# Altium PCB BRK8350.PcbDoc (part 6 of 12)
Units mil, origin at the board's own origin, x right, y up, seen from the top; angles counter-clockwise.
Board outline 9448.82 x 5905.51 mil, 8 copper layers (L1-TOP, L2-GND, L3-SIG, L4-GND, L5-PWR, L6-PWR, L7-GND, L8-BOT), stack 57.69 mil thick; 288 components, 543 nets, 1891 pads, 2032 vias.
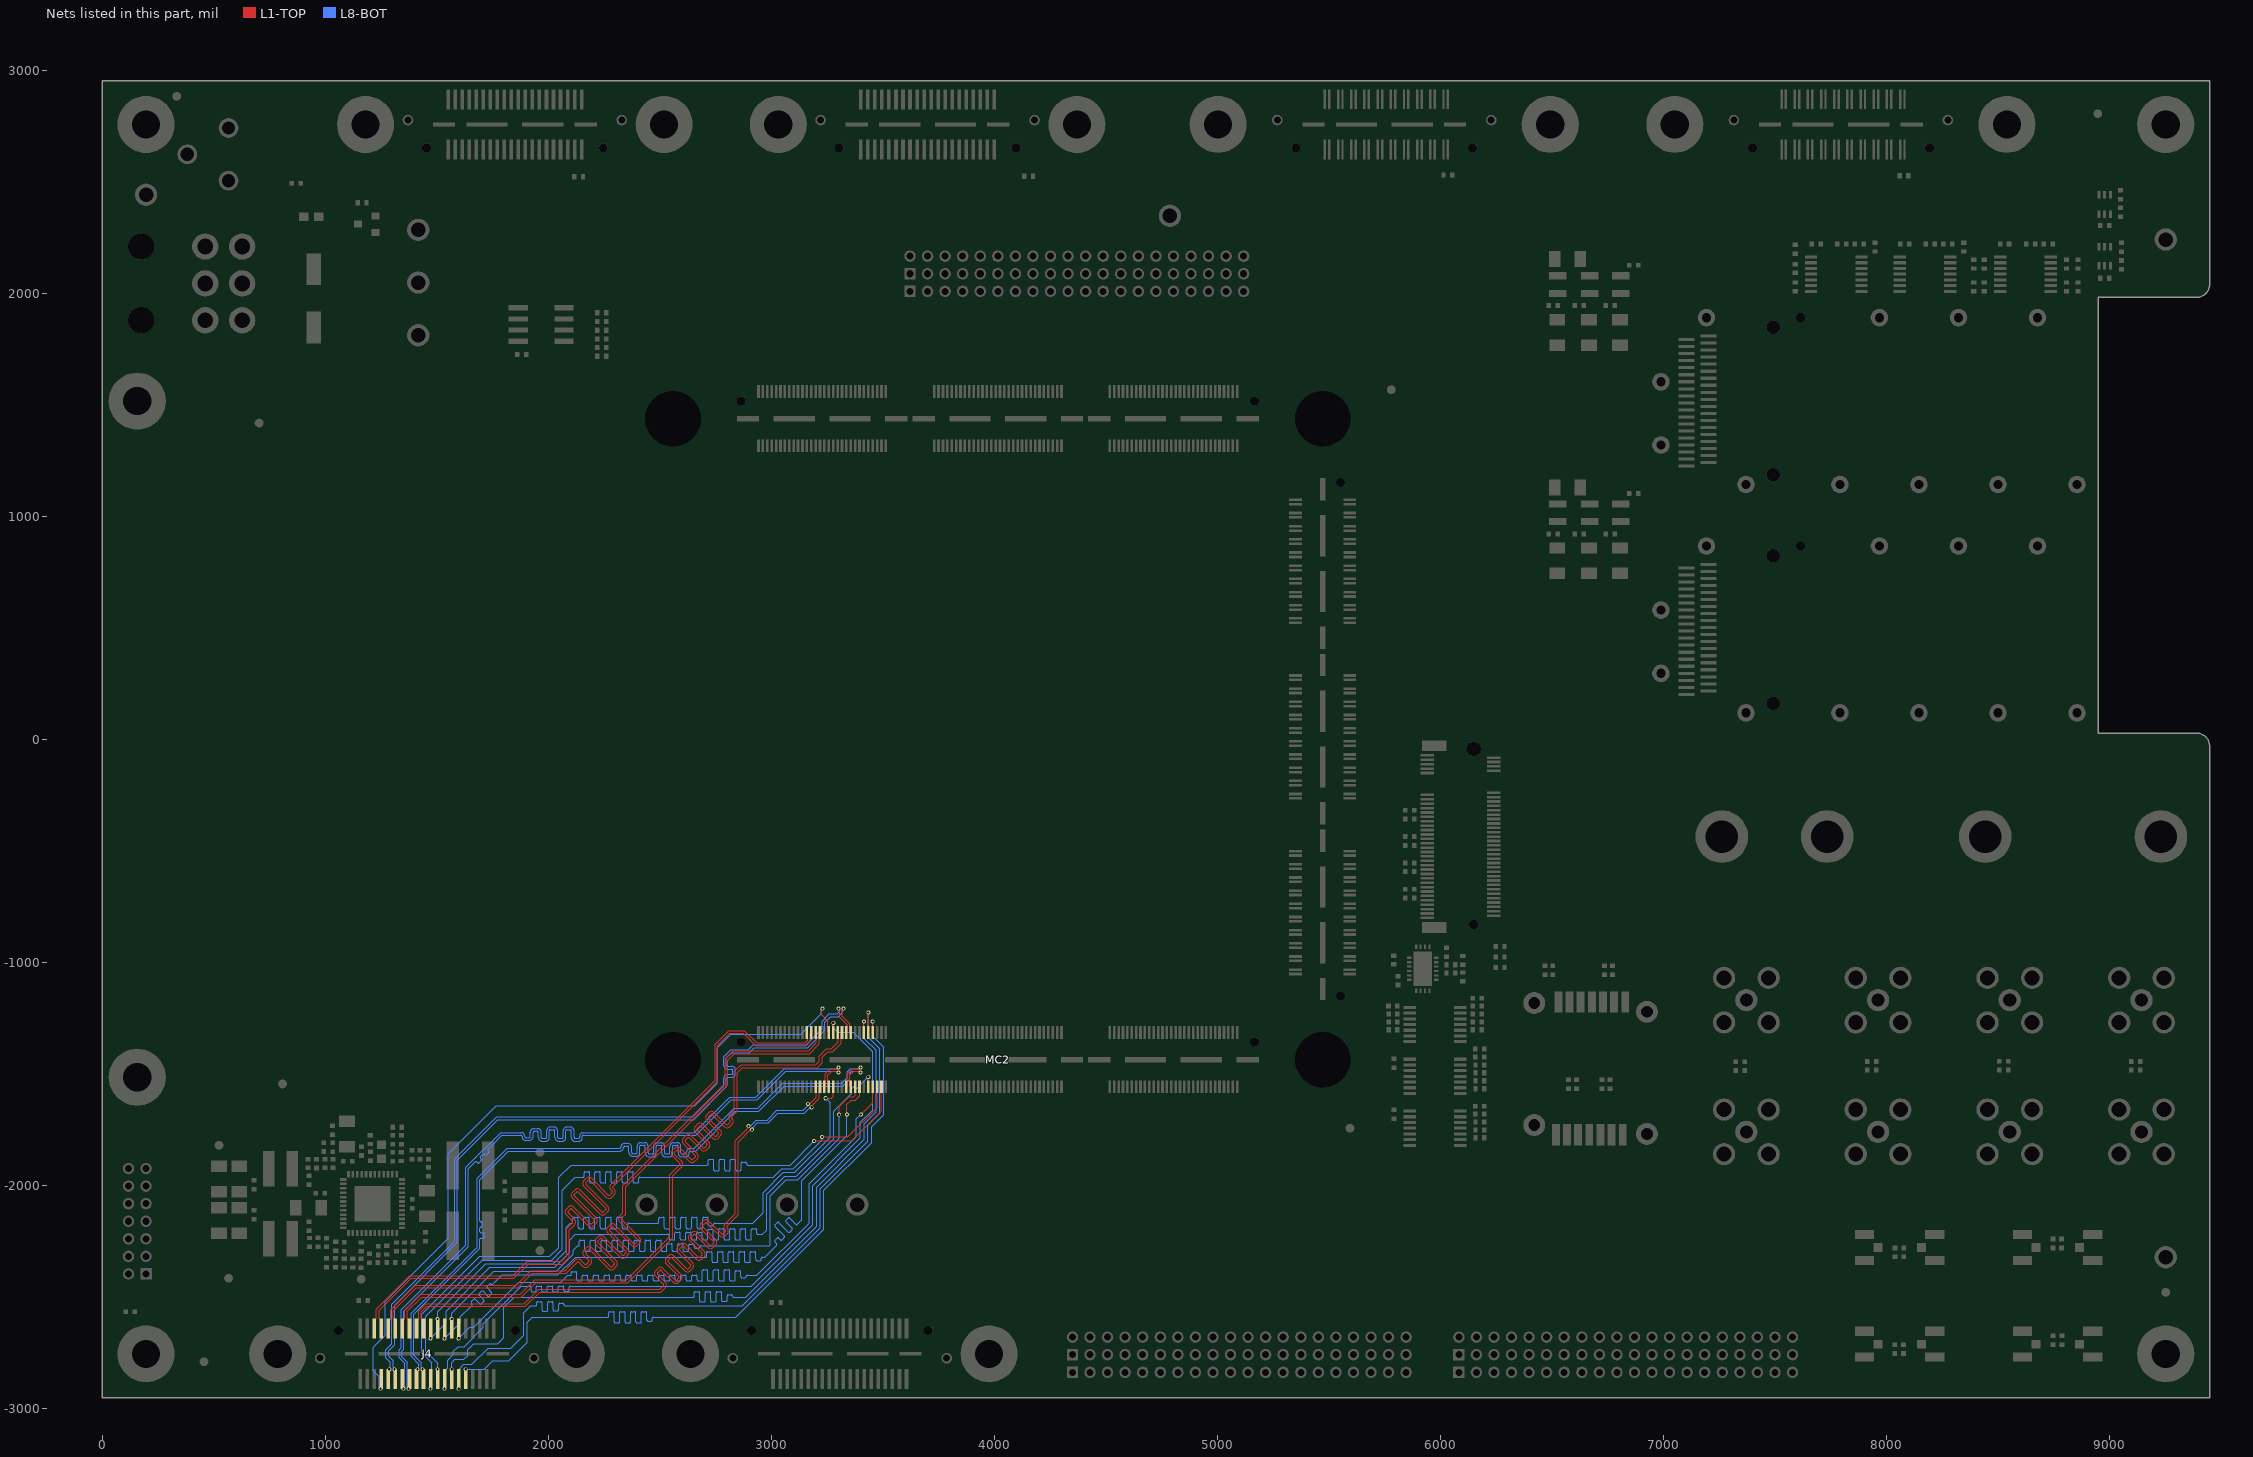
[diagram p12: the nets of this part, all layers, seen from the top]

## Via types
v1: diameter 18, hole 10, L1-TOP to L8-BOT, tented both sides, 2032 vias

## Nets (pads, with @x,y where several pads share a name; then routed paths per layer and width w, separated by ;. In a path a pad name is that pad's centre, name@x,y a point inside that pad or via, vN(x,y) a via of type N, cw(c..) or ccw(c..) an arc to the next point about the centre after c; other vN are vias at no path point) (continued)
PORTB_S1_D1P: J4.6 MC2.23 | length 3537.4
  L1-TOP w4.2: J4.6@1220.44,-2643.11 1220.44,-2606.36 1226.34,-2600.46 1227.43,-2600.46 1229.89,-2598 1229.89,-2555.26 1379.67,-2405.48 1840.24,-2405.48 1904.92,-2340.81 2058.46,-2340.81 2082.68,-2316.59 2082.68,-2207.32 2082.68,-2194.72 2091.59,-2185.81 2108.91,-2168.49 ccw(c2105.49,-2165.07) 2108.89,-2161.63 2079.99,-2132.72 cw(c2092.32,-2120.39) 2079.99,-2108.06 2090.25,-2097.79 cw(c2102.59,-2110.12) 2114.92,-2097.79 2188.76,-2171.64 ccw(c2192.19,-2168.22) 2195.61,-2171.64 2205.88,-2161.37 ccw(c2202.45,-2157.95) 2205.88,-2154.53 2107.93,-2056.58 cw(c2120.26,-2044.25) 2107.93,-2031.92 2118.2,-2021.65 cw(c2130.53,-2033.98) 2142.86,-2021.65 2240.81,-2119.59 ccw(c2244.23,-2116.17) 2247.65,-2119.59 2257.92,-2109.33 ccw(c2254.5,-2105.91) 2257.92,-2102.48 2159.98,-2004.54 cw(c2172.31,-1992.21) 2159.98,-1979.88 2170.24,-1969.61 cw(c2182.57,-1981.94) 2194.91,-1969.61 2269.7,-2044.4 ; 2269.7,-2044.4 ccw(c2273.12,-2040.98) 2276.55,-2044.4 ; 2276.55,-2044.4 2286.81,-2034.14 ccw(c2283.39,-2030.72) 2286.81,-2027.29 2280.79,-2021.27 cw(c2293.12,-2008.94) 2280.79,-1996.61 2286.73,-1990.67 2748.03,-1529.37 2748.03,-1368.01 2809.74,-1306.3 2879.23,-1306.3 2935.14,-1362.2 3150.98,-1362.2 3163.01,-1350.18 3163.01,-1318.88 MC2.23@3159.46,-1315.34
PORTB_S2_D0N: J4.7 MC2.33 | length 3378.8
  L1-TOP w4.2: v1(3229.36,-1208.57) 3228.43,-1208.57 3224.41,-1212.6 3224.41,-1234.15 3254.35,-1264.09 3254.35,-1311.8 MC2.33@3257.89,-1315.34
  L8-BOT w4.2: v1(1247.73,-2912.07) 1247.73,-2908.34 1242.49,-2903.1 1242.49,-2859.39 1214.64,-2831.54 1214.64,-2726.3 1269.03,-2671.92 1269.03,-2520.39 1551.18,-2238.23 1551.18,-1859.19 1767.85,-1642.52 2656.63,-1642.52 2757.41,-1541.74 2757.41,-1384.32 2818.9,-1322.83 2905.51,-1322.83 3131.66,-1322.83 3214.34,-1240.16 3224.41,-1230.08 3224.41,-1217.26 3229.36,-1212.31 v1(3229.36,-1208.57)
PORTB_S3_D1N: J4.8 MC2.25 | length 3537.5
  L1-TOP w4.2: J4.8@1251.94,-2643.11 1251.94,-2606.36 1246.04,-2600.46 1244.95,-2600.46 1242.49,-2598 1242.49,-2560.48 1384.89,-2418.08 1845.46,-2418.08 1910.14,-2353.41 2063.68,-2353.41 2095.28,-2321.81 2095.28,-2199.94 2100.5,-2194.72 2117.82,-2177.4 ccw(c2105.49,-2165.07) 2119.66,-2154.91 2119.66,-2154.58 2117.84,-2152.76 ; 2117.82,-2152.74 2088.9,-2123.81 cw(c2092.32,-2120.39) 2088.9,-2116.97 2099.16,-2106.7 cw(c2102.59,-2110.12) 2106.01,-2106.7 2179.85,-2180.55 ccw(c2192.19,-2168.22) 2204.52,-2180.55 2214.78,-2170.28 ccw(c2202.45,-2157.95) 2214.78,-2145.62 2116.84,-2047.67 cw(c2120.26,-2044.25) 2116.84,-2040.83 2127.11,-2030.56 cw(c2130.53,-2033.98) 2133.95,-2030.56 2231.9,-2128.5 ccw(c2244.23,-2116.17) 2256.56,-2128.5 2266.83,-2118.24 ccw(c2254.5,-2105.91) 2266.83,-2093.57 2168.89,-1995.63 cw(c2172.31,-1992.21) 2168.89,-1988.79 2179.15,-1978.52 cw(c2182.57,-1981.94) 2186,-1978.52 2260.79,-2053.31 ccw(c2273.12,-2040.98) 2285.46,-2053.31 2295.72,-2043.05 ccw(c2283.39,-2030.72) 2295.72,-2018.38 2289.7,-2012.36 cw(c2293.12,-2008.94) 2289.7,-2005.52 2295.64,-1999.58 2760.63,-1534.58 2760.63,-1373.23 2814.96,-1318.9 2874.02,-1318.9 2929.92,-1374.8 3156.2,-1374.8 3175.61,-1355.4 3175.61,-1318.88 MC2.25@3179.15,-1315.34
PORTB_S4_D2P: J4.9 MC2.41 | length 3378.6
  L1-TOP w4.2: v1(3301.35,-1208.66) 3303.81,-1211.12 3306.3,-1211.12 3306.3,-1247.23 3340.17,-1281.1 3340.17,-1311.8 MC2.41@3336.63,-1315.34
  L8-BOT w4.2: v1(1287.76,-2825.36) 1287.76,-2821.62 1292.26,-2817.12 1292.26,-2792.82 1272.24,-2772.8 1272.24,-2736.55 1298.23,-2710.56 1298.23,-2532.48 1580.38,-2250.33 1580.38,-1882.11 1769.58,-1692.91 2647.54,-1692.91 2786.61,-1553.84 2786.61,-1546.93 2786.61,-1520.73 cw(c2804.05,-1520.73) 2804.05,-1503.29 2821.89,-1503.29 ccw(c2821.89,-1498.45) 2826.73,-1498.45 2826.73,-1483.93 ccw(c2821.89,-1483.93) 2821.89,-1479.09 2804.05,-1479.09 cw(c2804.05,-1461.65) 2786.61,-1461.65 2786.61,-1453.25 2786.61,-1423.91 2817.62,-1392.91 2896.36,-1392.91 2919.19,-1370.08 3157.48,-1370.08 3228.29,-1299.27 3228.29,-1263.69 3260.48,-1231.49 3295.28,-1231.49 3306.3,-1220.47 3306.3,-1217.35 3301.35,-1212.4 v1(3301.35,-1208.66)
PORTB_S5_D3P: J4.10 MC2.27 | length 3537.5
  L1-TOP w4.2: J4.10@1283.44,-2643.11 1283.44,-2606.36 1289.34,-2600.46 1290.43,-2600.46 1292.89,-2598 1292.89,-2558.14 1403.75,-2447.28 1857.56,-2447.28 1922.23,-2382.61 2075.77,-2382.61 2092.95,-2365.43 2121.89,-2336.49 cw(c2134.22,-2348.82) 2144.38,-2334.65 2144.71,-2334.65 2146.53,-2336.47 ; 2146.56,-2336.49 2164.43,-2354.36 ccw(c2167.85,-2350.94) 2171.27,-2354.36 2181.54,-2344.09 ccw(c2178.12,-2340.67) 2181.54,-2337.25 2159.94,-2315.65 cw(c2172.27,-2303.32) 2159.94,-2290.99 2170.21,-2280.72 cw(c2182.54,-2293.05) 2194.87,-2280.72 2279.48,-2365.33 ccw(c2282.9,-2361.91) 2286.32,-2365.33 2296.59,-2355.06 ; 2296.59,-2355.06 ccw(c2293.17,-2351.64) 2296.59,-2348.22 2213.94,-2265.57 cw(c2226.27,-2253.24) 2213.94,-2240.9 2224.21,-2230.64 cw(c2236.54,-2242.97) 2248.87,-2230.64 2331.52,-2313.29 ccw(c2334.95,-2309.86) 2338.37,-2313.29 2348.64,-2303.02 ccw(c2345.21,-2299.6) 2348.64,-2296.17 2265.99,-2213.52 cw(c2278.32,-2201.19) 2265.98,-2188.86 2276.25,-2178.59 cw(c2288.58,-2190.93) 2300.92,-2178.59 2383.57,-2261.24 ccw(c2386.99,-2257.82) 2390.41,-2261.24 2400.68,-2250.98 ccw(c2397.26,-2247.55) 2400.68,-2244.13 2319.8,-2163.25 cw(c2332.13,-2150.92) 2319.8,-2138.59 2325.74,-2132.65 2334.65,-2123.74 2334.65,-2012.3 2334.65,-2001.87 2792.85,-1543.67 2792.85,-1433.43 2829.43,-1396.85 3167.03,-1396.85 3202.38,-1361.5 3202.38,-1318.88 MC2.27@3198.83,-1315.34
PORTB_S6_D2N: J4.11 MC2.43 | length 3379.2
  L1-TOP w4.2: v1(3323.85,-1208.66) 3321.36,-1208.66 3318.9,-1211.12 3318.9,-1242.01 3352.77,-1275.88 3352.77,-1311.8 MC2.43@3356.31,-1315.34
  L8-BOT w4.2: v1(1310.83,-2825.36) 1310.83,-2821.96 1304.86,-2816 1304.86,-2787.6 1284.84,-2767.58 1284.84,-2741.77 1310.83,-2715.78 1310.83,-2537.7 1592.98,-2255.55 1592.98,-1887.33 1774.8,-1705.51 2652.75,-1705.51 2799.21,-1559.06 2799.21,-1546.93 2799.21,-1520.73 cw(c2804.05,-1520.73) 2804.05,-1515.89 2821.89,-1515.89 ccw(c2821.89,-1498.45) 2839.33,-1498.45 2839.33,-1483.93 ccw(c2821.89,-1483.93) 2821.89,-1466.49 2804.05,-1466.49 cw(c2804.05,-1461.65) 2799.21,-1461.65 2799.21,-1453.25 2799.21,-1429.13 2822.83,-1405.51 2901.57,-1405.51 2924.41,-1382.68 3162.7,-1382.68 3240.89,-1304.49 3240.89,-1268.91 3265.7,-1244.09 3300.49,-1244.09 3318.9,-1225.69 3318.9,-1217.35 3323.85,-1212.4 v1(3323.85,-1208.66)
PORTB_S7_D3N: J4.12 MC2.29 | length 3537.4
  L1-TOP w4.2: J4.12@1314.94,-2643.11 1314.94,-2606.36 1309.04,-2600.46 1307.95,-2600.46 1305.49,-2598 1305.49,-2563.36 1408.97,-2459.88 1862.78,-2459.88 1927.45,-2395.21 2080.99,-2395.21 2101.86,-2374.34 2130.8,-2345.4 cw(c2134.22,-2348.82) 2137.67,-2345.42 2155.52,-2363.27 ccw(c2167.85,-2350.94) 2180.18,-2363.27 2190.45,-2353 ccw(c2178.12,-2340.67) 2190.45,-2328.34 2168.85,-2306.74 cw(c2172.27,-2303.32) 2168.85,-2299.9 2179.12,-2289.63 cw(c2182.54,-2293.05) 2185.96,-2289.63 2270.57,-2374.24 ccw(c2282.9,-2361.91) 2295.23,-2374.24 2305.5,-2363.97 ccw(c2293.17,-2351.64) 2305.5,-2339.31 2222.85,-2256.66 cw(c2226.27,-2253.24) 2222.85,-2249.81 2233.12,-2239.55 cw(c2236.54,-2242.97) 2239.96,-2239.55 2322.61,-2322.2 ccw(c2334.95,-2309.86) 2347.28,-2322.2 2357.54,-2311.93 ccw(c2345.21,-2299.6) 2357.54,-2287.26 2274.89,-2204.61 cw(c2278.32,-2201.19) 2274.89,-2197.77 2285.16,-2187.5 cw(c2288.58,-2190.93) 2292.01,-2187.5 2374.66,-2270.15 ccw(c2386.99,-2257.82) 2399.32,-2270.15 2409.59,-2259.89 ccw(c2397.26,-2247.55) 2409.59,-2235.22 2328.71,-2154.34 cw(c2332.13,-2150.92) 2328.71,-2147.5 2334.65,-2141.56 2347.25,-2128.96 2347.25,-2007.09 2805.45,-1548.88 2805.45,-1438.65 2834.65,-1409.45 3172.25,-1409.45 3214.98,-1366.72 3214.98,-1318.88 MC2.29@3218.52,-1315.34
PORTB_S8_D4P: J4.13 MC2.32 | length 3380
  L1-TOP w4.2: MC2.32@3238.2,-1558.65 3241.75,-1555.1 3241.75,-1500.29 3265.29,-1476.75 3299,-1476.75 3299,-1474.26 v1(3301.46,-1471.8)
  L8-BOT w4.2: v1(1350.66,-2912.07) 1350.66,-2908.34 1355.89,-2903.1 1355.89,-2798.95 1331.17,-2774.22 1331.17,-2738.64 1340.13,-2729.68 1340.13,-2559.32 1629.81,-2269.63 1629.81,-1920.3 1786.33,-1763.78 1850.39,-1763.78 1877.79,-1763.78 cw(c1877.79,-1781.22) 1895.23,-1781.22 ccw(c1900.07,-1781.22) 1900.07,-1786.06 1914.59,-1786.06 ccw(c1914.59,-1781.22) 1919.43,-1781.22 1919.43,-1763.28 cw(c1936.87,-1763.28) 1936.87,-1745.84 1951.39,-1745.84 cw(c1951.39,-1763.28) 1968.83,-1763.28 1968.83,-1785.26 ccw(c1973.67,-1785.26) 1973.67,-1790.1 1988.19,-1790.1 ccw(c1988.19,-1785.26) 1993.03,-1785.26 1993.03,-1756.22 cw(c2010.47,-1756.22) 2010.47,-1738.78 2024.99,-1738.78 cw(c2024.99,-1756.22) 2042.43,-1756.22 2042.43,-1785.26 ccw(c2047.27,-1785.26) 2047.27,-1790.1 2061.79,-1790.1 ccw(c2061.79,-1785.26) 2066.63,-1785.26 2066.63,-1756.22 cw(c2084.07,-1756.22) 2084.07,-1738.78 2098.59,-1738.78 cw(c2098.59,-1756.22) 2116.03,-1756.22 2116.03,-1785.26 ccw(c2120.87,-1785.26) 2120.87,-1790.1 2135.39,-1790.1 ccw(c2135.39,-1785.26) 2140.23,-1785.26 2140.23,-1781.22 cw(c2157.67,-1781.22) 2157.67,-1763.78 2166.07,-1763.78 2655.41,-1763.78 2814.6,-1604.59 2930.84,-1604.59 3058.68,-1476.75 3292.77,-1476.75 3297.72,-1471.8 v1(3301.46,-1471.8)
PORTB_S9_D5P: J4.14 MC2.37 | length 3537.4
  L1-TOP w4.2: J4.14@1346.44,-2643.11 1346.44,-2606.36 1352.34,-2600.46 1353.43,-2600.46 1355.89,-2598 1355.89,-2559.84 1426.65,-2489.08 1874.87,-2489.08 1939.55,-2424.41 2351.18,-2424.41 2545.6,-2229.99 2545.6,-1952.33 2569.83,-1928.1 2589.6,-1908.33 ccw(c2586.18,-1904.91) 2589.58,-1901.47 ; 2589.56,-1901.45 2556.98,-1868.87 cw(c2569.31,-1856.53) 2556.98,-1844.2 2567.24,-1833.93 cw(c2579.58,-1846.27) 2591.91,-1833.93 2642.21,-1884.23 ccw(c2645.63,-1880.81) 2649.05,-1884.23 2659.32,-1873.97 ccw(c2655.9,-1870.54) 2659.32,-1867.12 2606.24,-1814.05 cw(c2618.58,-1801.71) 2606.24,-1789.38 2616.51,-1779.12 cw(c2628.84,-1791.45) 2641.17,-1779.11 2694.25,-1832.19 ccw(c2697.67,-1828.77) 2701.09,-1832.19 2711.36,-1821.92 ccw(c2707.94,-1818.5) 2711.36,-1815.08 2658.29,-1762 cw(c2670.62,-1749.67) 2658.29,-1737.34 2668.55,-1727.07 cw(c2680.89,-1739.4) 2693.22,-1727.07 2746.29,-1780.15 ccw(c2749.71,-1776.72) 2753.14,-1780.15 2763.4,-1769.88 ccw(c2759.98,-1766.46) 2763.4,-1763.04 2710.33,-1709.96 cw(c2722.66,-1697.63) 2710.33,-1685.3 2720.6,-1675.03 cw(c2732.93,-1687.36) 2745.26,-1675.03 2798.34,-1728.1 ccw(c2801.76,-1724.68) 2805.18,-1728.1 2815.45,-1717.84 ccw(c2812.03,-1714.41) 2815.45,-1710.99 2813.52,-1709.07 cw(c2825.86,-1696.74) 2813.52,-1684.41 2819.46,-1678.47 2834.65,-1663.28 2834.65,-1489.64 2864.65,-1459.63 3200.17,-1459.63 3214.92,-1444.87 3214.92,-1421.22 3247.42,-1388.73 3269.55,-1388.73 3300.8,-1357.48 3300.8,-1318.88 MC2.37@3297.26,-1315.34
PORTB_S10_D4N: J4.15 MC2.34 | length 3380
  L1-TOP w4.2: MC2.34@3257.89,-1558.65 3254.35,-1555.1 3254.35,-1505.51 3270.51,-1489.35 3299,-1489.35 3301.46,-1491.81 v1(3301.46,-1494.3)
  L8-BOT w4.2: v1(1373.73,-2912.07) 1373.73,-2908.34 1368.49,-2903.1 1368.49,-2793.73 1343.77,-2769 1343.77,-2743.86 1352.73,-2734.9 1352.73,-2564.54 1642.41,-2274.85 1642.41,-1925.52 1653.58,-1914.35 1672.18,-1895.76 cw(c1675.6,-1899.18) 1679.02,-1895.76 1683,-1899.74 ccw(c1686.42,-1896.32) 1689.85,-1899.74 1700.11,-1889.47 ccw(c1696.69,-1886.05) 1700.11,-1882.63 1696.13,-1878.64 cw(c1699.55,-1875.22) 1696.13,-1871.8 1706.4,-1861.53 cw(c1709.82,-1864.95) 1713.24,-1861.53 1716.21,-1864.5 ccw(c1719.63,-1861.08) 1723.06,-1864.5 1733.32,-1854.23 ccw(c1729.9,-1850.81) 1733.32,-1847.39 1730.36,-1844.42 cw(c1733.78,-1841) 1730.36,-1837.58 1750.35,-1817.58 1791.55,-1776.38 1850.39,-1776.38 1877.79,-1776.38 cw(c1877.79,-1781.22) 1882.63,-1781.22 ccw(c1900.07,-1781.22) 1900.07,-1798.66 1914.59,-1798.66 ccw(c1914.59,-1781.22) 1932.03,-1781.22 1932.03,-1763.28 cw(c1936.87,-1763.28) 1936.87,-1758.44 1951.39,-1758.44 cw(c1951.39,-1763.28) 1956.23,-1763.28 1956.23,-1785.26 ccw(c1973.67,-1785.26) 1973.67,-1802.7 1988.19,-1802.7 ccw(c1988.19,-1785.26) 2005.63,-1785.26 2005.63,-1756.22 cw(c2010.47,-1756.22) 2010.47,-1751.38 2024.99,-1751.38 cw(c2024.99,-1756.22) 2029.83,-1756.22 2029.83,-1785.26 ccw(c2047.27,-1785.26) 2047.27,-1802.7 2061.79,-1802.7 ccw(c2061.79,-1785.26) 2079.23,-1785.26 2079.23,-1756.22 cw(c2084.07,-1756.22) 2084.07,-1751.38 2098.59,-1751.38 cw(c2098.59,-1756.22) 2103.43,-1756.22 2103.43,-1785.26 ccw(c2120.87,-1785.26) 2120.87,-1802.7 2135.39,-1802.7 ccw(c2135.39,-1785.26) 2152.83,-1785.26 2152.83,-1781.22 cw(c2157.67,-1781.22) 2157.67,-1776.38 2166.07,-1776.38 2660.63,-1776.38 2819.82,-1617.19 2936.06,-1617.19 3063.9,-1489.35 3292.77,-1489.35 3297.72,-1494.3 v1(3301.46,-1494.3)
PORTB_S11_D5N: J4.16 MC2.39 | length 3537.5
  L1-TOP w4.2: J4.16@1377.94,-2643.11 1377.94,-2606.36 1372.04,-2600.46 1370.95,-2600.46 1368.49,-2598 1368.49,-2565.06 1431.87,-2501.68 1880.09,-2501.68 1944.76,-2437.01 2356.4,-2437.01 2558.2,-2235.21 2558.2,-1957.54 2578.74,-1937.01 2598.51,-1917.24 ccw(c2586.18,-1904.91) 2600.35,-1894.75 2600.35,-1894.42 2598.53,-1892.6 2565.89,-1859.96 cw(c2569.31,-1856.53) 2565.89,-1853.11 2576.15,-1842.84 cw(c2579.58,-1846.27) 2583,-1842.84 2633.3,-1893.14 ccw(c2645.63,-1880.81) 2657.96,-1893.14 2668.23,-1882.88 ccw(c2655.9,-1870.54) 2668.23,-1858.21 2615.15,-1805.14 cw(c2618.58,-1801.71) 2615.15,-1798.29 2625.42,-1788.02 cw(c2628.84,-1791.45) 2632.26,-1788.02 2685.34,-1841.1 ccw(c2697.67,-1828.77) 2710,-1841.1 2720.27,-1830.83 ccw(c2707.94,-1818.5) 2720.27,-1806.17 2667.2,-1753.09 cw(c2670.62,-1749.67) 2667.2,-1746.25 2677.46,-1735.98 cw(c2680.89,-1739.4) 2684.31,-1735.98 2737.38,-1789.06 ccw(c2749.71,-1776.72) 2762.05,-1789.06 2772.31,-1778.79 ccw(c2759.98,-1766.46) 2772.31,-1754.13 2719.24,-1701.05 cw(c2722.66,-1697.63) 2719.24,-1694.21 2729.51,-1683.94 cw(c2732.93,-1687.36) 2736.35,-1683.94 2789.43,-1737.01 ccw(c2801.76,-1724.68) 2814.09,-1737.01 2824.36,-1726.75 ccw(c2812.03,-1714.41) 2824.36,-1702.08 2822.43,-1700.16 cw(c2825.86,-1696.74) 2822.43,-1693.31 2828.37,-1687.37 2847.25,-1668.5 2847.25,-1494.86 2869.87,-1472.23 3205.38,-1472.23 3227.52,-1450.09 3227.52,-1426.44 3252.63,-1401.33 3274.77,-1401.33 3313.4,-1362.7 3313.4,-1318.88 MC2.39@3316.94,-1315.34
PORTB_S12_D6P: J4.17 MC2.42 | length 3380
  L1-TOP w4.2: MC2.42@3336.63,-1558.65 3340.17,-1555.1 3340.17,-1500.29 3363.71,-1476.75 3397.42,-1476.75 3397.42,-1474.26 v1(3399.88,-1471.8)
  L8-BOT w4.2: v1(1413.76,-2825.36) 1413.76,-2821.62 1418.99,-2816.39 1418.99,-2801.74 1385.04,-2767.79 1385.04,-2573.52 1681.1,-2277.46 1681.1,-1969.09 1815.55,-1834.65 2228.35,-1834.65 2320.19,-1834.65 ccw(c2320.19,-1829.81) 2325.03,-1829.81 ; 2325.03,-1829.8 cw(c2342.47,-1829.8) 2342.47,-1812.36 2356.99,-1812.36 cw(c2356.99,-1829.8) 2374.43,-1829.8 2374.43,-1852.97 ccw(c2379.27,-1852.97) 2379.27,-1857.81 2393.79,-1857.81 ccw(c2393.79,-1852.97) 2398.63,-1852.97 2398.63,-1825.94 cw(c2416.07,-1825.94) 2416.07,-1808.5 2430.59,-1808.5 cw(c2430.59,-1825.94) 2448.03,-1825.94 2448.03,-1854.81 ccw(c2452.87,-1854.81) 2452.87,-1859.65 2467.39,-1859.65 ccw(c2467.39,-1854.81) 2472.23,-1854.81 2472.23,-1825.94 cw(c2489.67,-1825.94) 2489.67,-1808.5 2504.19,-1808.5 cw(c2504.19,-1825.94) 2521.63,-1825.94 2521.63,-1854.81 ccw(c2526.47,-1854.81) 2526.47,-1859.65 2540.99,-1859.65 ccw(c2540.99,-1854.81) 2545.83,-1854.81 2545.83,-1825.94 cw(c2563.27,-1825.94) 2563.27,-1808.5 2577.79,-1808.5 cw(c2577.79,-1825.94) 2595.23,-1825.94 2595.23,-1854.81 ccw(c2600.07,-1854.81) 2600.07,-1859.65 2614.59,-1859.65 ccw(c2614.59,-1854.81) 2619.43,-1854.81 2619.43,-1852.09 cw(c2636.87,-1852.09) 2636.87,-1834.65 2645.27,-1834.65 2655.41,-1834.65 2834.29,-1655.77 2938.78,-1655.77 3052.03,-1542.52 3315.75,-1542.52 3339.62,-1518.65 3339.62,-1492.03 3354.9,-1476.75 3391.2,-1476.75 3396.15,-1471.8 v1(3399.88,-1471.8)
PORTB_S13_D7P: J4.18 MC2.28 | length 3427
  L1-TOP w4.2: J4.18@1409.44,-2643.11 1409.44,-2606.36 1415.34,-2600.46 1416.43,-2600.46 1418.89,-2598 1418.89,-2561.88 1449.89,-2530.88 1892.19,-2530.88 1956.86,-2466.21 2500.23,-2466.21 2502.39,-2464.04 2516.27,-2450.16 ccw(c2512.85,-2446.74) 2516.25,-2443.3 ; 2516.24,-2443.29 2481.26,-2408.31 cw(c2493.59,-2395.98) 2481.26,-2383.65 2491.53,-2373.38 cw(c2503.86,-2385.71) 2516.19,-2373.38 2568.88,-2426.07 ccw(c2572.3,-2422.64) 2575.72,-2426.07 2585.99,-2415.8 ccw(c2582.57,-2412.38) 2585.99,-2408.95 2528.76,-2351.73 cw(c2541.09,-2339.4) 2528.76,-2327.06 2539.03,-2316.8 cw(c2551.36,-2329.13) 2563.69,-2316.8 2620.92,-2374.02 ccw(c2624.34,-2370.6) 2627.77,-2374.02 2638.03,-2363.76 ccw(c2634.61,-2360.33) 2638.03,-2356.91 2580.81,-2299.68 cw(c2593.14,-2287.35) 2580.81,-2275.02 2591.07,-2264.75 cw(c2603.4,-2277.09) 2615.74,-2264.75 2672.96,-2321.98 ccw(c2676.39,-2318.56) 2679.81,-2321.98 2690.08,-2311.71 ccw(c2686.65,-2308.29) 2690.08,-2304.87 2632.85,-2247.64 cw(c2645.18,-2235.31) 2632.85,-2222.98 2643.12,-2212.71 cw(c2655.45,-2225.04) 2667.78,-2212.71 2725.01,-2269.94 ccw(c2728.43,-2266.52) 2731.85,-2269.94 2742.12,-2259.67 ccw(c2738.7,-2256.25) 2742.12,-2252.83 2684.89,-2195.6 cw(c2697.22,-2183.27) 2684.89,-2170.94 2695.16,-2160.67 cw(c2707.49,-2173) 2719.82,-2160.67 2777.05,-2217.89 ccw(c2780.47,-2214.47) 2783.89,-2217.89 2794.16,-2207.63 ccw(c2790.74,-2204.21) 2794.16,-2200.78 2792.24,-2198.86 cw(c2804.57,-2186.53) 2792.24,-2174.2 2798.18,-2168.26 2838.58,-2127.85 2838.58,-1801.08 2896.6,-1743.06 2896.6,-1736.06 v1(2897.56,-1735.1) ; v1(3165.29,-1634.81) 3166.24,-1633.86 3173.24,-1633.86 3202.38,-1604.73 3202.38,-1562.19 MC2.28@3198.83,-1558.65
  L8-BOT w4.2: v1(2897.56,-1735.1) 2900.2,-1732.46 2907.2,-1732.46 2931.79,-1707.87 2981.1,-1707.87 3024.41,-1664.57 3142.54,-1664.57 3162.65,-1644.45 3162.65,-1637.45 v1(3165.29,-1634.81)
PORTB_S14_D6N: J4.19 MC2.44 | length 3380
  L1-TOP w4.2: MC2.44@3356.31,-1558.65 3352.77,-1555.1 3352.77,-1505.51 3368.93,-1489.35 3397.42,-1489.35 3399.88,-1491.81 v1(3399.88,-1494.3)
  L8-BOT w4.2: v1(1436.83,-2825.36) 1436.83,-2821.62 1431.59,-2816.39 1431.59,-2796.52 1397.64,-2762.57 1397.64,-2578.74 1693.7,-2282.68 1693.7,-2267.72 1693.7,-2241.42 cw(c1698.54,-2241.42) 1698.54,-2236.58 1708.19,-2236.58 ccw(c1708.19,-2231.74) 1713.03,-2231.74 1713.03,-2217.22 ccw(c1708.19,-2217.22) 1708.19,-2212.38 1698.54,-2212.38 cw(c1698.54,-2207.54) 1693.7,-2207.54 1693.7,-2193.02 cw(c1698.54,-2193.02) 1698.54,-2188.18 1698.73,-2188.18 ccw(c1698.73,-2183.34) 1703.57,-2183.34 1703.57,-2168.82 ccw(c1698.73,-2168.82) 1698.73,-2163.98 1698.54,-2163.98 cw(c1698.54,-2159.14) 1693.7,-2159.14 1693.7,-2145.67 1693.7,-1974.31 1820.77,-1847.25 2228.35,-1847.25 2320.19,-1847.25 ccw(c2320.19,-1829.81) 2337.63,-1829.81 ; 2337.63,-1829.8 cw(c2342.47,-1829.8) 2342.47,-1824.96 2356.99,-1824.96 cw(c2356.99,-1829.8) 2361.83,-1829.8 2361.83,-1852.97 ccw(c2379.27,-1852.97) 2379.27,-1870.41 2393.79,-1870.41 ccw(c2393.79,-1852.97) 2411.23,-1852.97 2411.23,-1825.94 cw(c2416.07,-1825.94) 2416.07,-1821.1 2430.59,-1821.1 cw(c2430.59,-1825.94) 2435.43,-1825.94 2435.43,-1854.81 ccw(c2452.87,-1854.81) 2452.87,-1872.25 2467.39,-1872.25 ccw(c2467.39,-1854.81) 2484.83,-1854.81 2484.83,-1825.94 cw(c2489.67,-1825.94) 2489.67,-1821.1 2504.19,-1821.1 cw(c2504.19,-1825.94) 2509.03,-1825.94 2509.03,-1854.81 ccw(c2526.47,-1854.81) 2526.47,-1872.25 2540.99,-1872.25 ccw(c2540.99,-1854.81) 2558.43,-1854.81 2558.43,-1825.94 cw(c2563.27,-1825.94) 2563.27,-1821.1 2577.79,-1821.1 cw(c2577.79,-1825.94) 2582.63,-1825.94 2582.63,-1854.81 ccw(c2600.07,-1854.81) 2600.07,-1872.25 2614.59,-1872.25 ccw(c2614.59,-1854.81) 2632.03,-1854.81 2632.03,-1852.09 cw(c2636.87,-1852.09) 2636.87,-1847.25 2645.27,-1847.25 2660.63,-1847.25 2839.5,-1668.37 2944,-1668.37 3057.25,-1555.12 3320.97,-1555.12 3352.22,-1523.87 3352.22,-1497.25 3360.12,-1489.35 3391.2,-1489.35 3396.15,-1494.3 v1(3399.88,-1494.3)
PORTB_S15_D7N: J4.20 MC2.30 | length 3427.1
  L1-TOP w4.2: J4.20@1440.94,-2643.11 1440.94,-2606.36 1435.04,-2600.46 1433.95,-2600.46 1431.49,-2598 1431.49,-2567.1 1455.11,-2543.48 1897.41,-2543.48 1962.08,-2478.81 2505.44,-2478.81 2511.3,-2472.95 2525.18,-2459.07 ccw(c2512.85,-2446.74) 2527.02,-2436.58 2527.02,-2436.26 2525.18,-2434.41 2490.17,-2399.4 cw(c2493.59,-2395.98) 2490.17,-2392.56 2500.44,-2382.29 cw(c2503.86,-2385.71) 2507.28,-2382.29 2559.97,-2434.98 ccw(c2572.3,-2422.64) 2584.63,-2434.98 2594.9,-2424.71 ccw(c2582.57,-2412.38) 2594.9,-2400.04 2537.67,-2342.82 cw(c2541.09,-2339.4) 2537.67,-2335.97 2547.94,-2325.71 cw(c2551.36,-2329.13) 2554.78,-2325.71 2612.01,-2382.93 ccw(c2624.34,-2370.6) 2636.67,-2382.93 2646.94,-2372.67 ccw(c2634.61,-2360.33) 2646.94,-2348 2589.71,-2290.78 cw(c2593.14,-2287.35) 2589.71,-2283.93 2599.98,-2273.66 cw(c2603.4,-2277.09) 2606.83,-2273.66 2664.05,-2330.89 ccw(c2676.39,-2318.56) 2688.72,-2330.89 2698.98,-2320.62 ccw(c2686.65,-2308.29) 2698.98,-2295.96 2641.76,-2238.73 cw(c2645.18,-2235.31) 2641.76,-2231.89 2652.02,-2221.62 cw(c2655.45,-2225.04) 2658.87,-2221.62 2716.1,-2278.85 ccw(c2728.43,-2266.52) 2740.76,-2278.85 2751.03,-2268.58 ccw(c2738.7,-2256.25) 2751.03,-2243.92 2693.8,-2186.69 cw(c2697.22,-2183.27) 2693.8,-2179.84 2704.07,-2169.58 cw(c2707.49,-2173) 2710.91,-2169.58 2768.14,-2226.8 ccw(c2780.47,-2214.47) 2792.8,-2226.8 2803.07,-2216.54 ccw(c2790.74,-2204.21) 2803.07,-2191.87 2801.15,-2189.95 cw(c2804.57,-2186.53) 2801.15,-2183.11 2807.09,-2177.17 2851.18,-2133.07 2851.18,-1806.3 2905.51,-1751.97 2912.51,-1751.97 v1(2913.47,-1751.01) ; v1(3181.2,-1650.72) 3182.15,-1649.77 3182.15,-1642.77 3214.98,-1609.94 3214.98,-1562.19 MC2.30@3218.52,-1558.65
  L8-BOT w4.2: v1(2913.47,-1751.01) 2916.11,-1748.37 2916.11,-1741.37 2937.01,-1720.47 2986.32,-1720.47 3029.63,-1677.17 3147.76,-1677.17 3171.56,-1653.36 3178.56,-1653.36 v1(3181.2,-1650.72)
PORTB_S16: J4.21 MC2.58 | length 3377
  L1-TOP w4.5: v1(3192.55,-1801.08) 3360.34,-1801.08 3494.11,-1667.31 MC2.58@3494.11,-1558.65
  L8-BOT w4.5: v1(1472.54,-2912.07) 1472.54,-2874.87 1477.38,-2870.03 1477.38,-2794.85 1433.07,-2750.54 1433.07,-2578.74 1692.91,-2318.9 2007.86,-2318.9 2047.24,-2279.52 2047.24,-1964.57 2102.36,-1909.45 2710.35,-1909.45 2712.6,-1909.45 ccw(c2712.6,-1904.55) 2717.5,-1904.55 2717.5,-1889.35 cw(c2722.4,-1889.35) 2722.4,-1884.45 2737.1,-1884.45 cw(c2737.1,-1889.35) 2742,-1889.35 2742,-1929.55 ccw(c2746.9,-1929.55) 2746.9,-1934.45 2761.6,-1934.45 ccw(c2761.6,-1929.55) 2766.5,-1929.55 2766.5,-1889.35 cw(c2771.4,-1889.35) 2771.4,-1884.45 2786.1,-1884.45 cw(c2786.1,-1889.35) 2791,-1889.35 2791,-1929.55 ccw(c2795.9,-1929.55) 2795.9,-1934.45 2810.6,-1934.45 ccw(c2810.6,-1929.55) 2815.5,-1929.55 2815.5,-1889.35 cw(c2820.4,-1889.35) 2820.4,-1884.45 2835.1,-1884.45 cw(c2835.1,-1889.35) 2840,-1889.35 2840,-1929.55 ccw(c2844.9,-1929.55) 2844.9,-1934.45 2859.6,-1934.45 ccw(c2859.6,-1929.55) 2864.5,-1929.55 2864.5,-1901.73 cw(c2869.4,-1901.73) 2869.4,-1896.83 2884.1,-1896.83 cw(c2884.1,-1901.73) 2889,-1901.73 2889,-1904.55 ccw(c2893.9,-1904.55) 2893.9,-1909.45 3035.43,-1909.45 3084.18,-1909.45 v1(3192.55,-1801.08)
PORTB_S17: J4.22 MC2.52 | length 3377
  L1-TOP w4.5: MC2.52@3435.06,-1558.65 v1(3435.06,-1513.8)
  L8-BOT w4.5: v1(1472.54,-2686.47) 1541.89,-2617.12 1541.89,-2564.27 1737.61,-2368.55 2029.99,-2368.55 2029.99,-2366.99 2096.74,-2300.23 2096.74,-2245.78 2122.05,-2220.47 2511.81,-2220.47 2538.56,-2220.47 cw(c2538.56,-2225.37) 2543.46,-2225.37 2543.46,-2240.57 ccw(c2548.36,-2240.57) 2548.36,-2245.47 2563.06,-2245.47 ccw(c2563.06,-2240.57) 2567.96,-2240.57 2567.96,-2215.69 cw(c2572.86,-2215.69) 2572.86,-2210.79 2587.56,-2210.79 cw(c2587.56,-2215.69) 2592.46,-2215.69 2592.46,-2240.57 ccw(c2597.36,-2240.57) 2597.36,-2245.47 2612.06,-2245.47 ccw(c2612.06,-2240.57) 2616.96,-2240.57 2616.96,-2215.69 cw(c2621.86,-2215.69) 2621.86,-2210.79 2636.56,-2210.79 cw(c2636.56,-2215.69) 2641.46,-2215.69 2641.46,-2240.57 ccw(c2646.36,-2240.57) 2646.36,-2245.47 2661.06,-2245.47 ccw(c2661.06,-2240.57) 2665.96,-2240.57 2665.96,-2215.69 cw(c2670.86,-2215.69) 2670.86,-2210.79 2685.56,-2210.79 cw(c2685.56,-2215.69) 2690.46,-2215.69 2690.46,-2240.57 ccw(c2695.36,-2240.57) 2695.36,-2245.47 2710.06,-2245.47 ccw(c2710.06,-2240.57) 2714.96,-2240.57 2714.96,-2203.24 cw(c2719.86,-2203.24) 2719.86,-2198.34 2734.56,-2198.34 cw(c2734.56,-2203.24) 2739.46,-2203.24 2739.46,-2240.57 ccw(c2744.36,-2240.57) 2744.36,-2245.47 2759.06,-2245.47 ccw(c2759.06,-2240.57) 2763.96,-2240.57 2763.96,-2200.37 cw(c2768.86,-2200.37) 2768.86,-2195.47 2783.56,-2195.47 cw(c2783.56,-2200.37) 2788.46,-2200.37 2788.46,-2240.57 ccw(c2793.36,-2240.57) 2793.36,-2245.47 2808.06,-2245.47 ccw(c2808.06,-2240.57) 2812.96,-2240.57 2812.96,-2200.37 cw(c2817.86,-2200.37) 2817.86,-2195.47 2832.56,-2195.47 cw(c2832.56,-2200.37) 2837.46,-2200.37 2837.46,-2240.57 ccw(c2842.36,-2240.57) 2842.36,-2245.47 2857.06,-2245.47 ccw(c2857.06,-2240.57) 2861.96,-2240.57 2861.96,-2200.37 cw(c2866.86,-2200.37) 2866.86,-2195.47 2881.56,-2195.47 cw(c2881.56,-2200.37) 2886.46,-2200.37 2886.46,-2240.57 ccw(c2891.36,-2240.57) 2891.36,-2245.47 2906.06,-2245.47 ccw(c2906.06,-2240.57) 2910.96,-2240.57 2910.96,-2200.37 cw(c2915.86,-2200.37) 2915.86,-2195.47 2930.56,-2195.47 cw(c2930.56,-2200.37) 2935.46,-2200.37 2935.46,-2215.57 ccw(c2940.36,-2215.57) 2940.36,-2220.47 2952.76,-2220.47 2960.5,-2220.47 2979.56,-2201.41 2979.56,-2040.41 3060.87,-1959.1 3112.02,-1959.1 3280.28,-1790.84 3280.28,-1668.57 3358.81,-1590.04 3360.4,-1588.45 ccw(c3356.94,-1584.98) 3360.4,-1581.52 3356.11,-1577.23 cw(c3359.57,-1573.76) 3356.11,-1570.3 3366.5,-1559.9 cw(c3369.97,-1563.37) 3373.43,-1559.9 3377.73,-1564.19 ccw(c3381.19,-1560.73) 3384.66,-1564.19 3415.37,-1533.48 v1(3435.06,-1513.8)
PORTB_S18: J4.23 MC2.56 | length 3377
  L1-TOP w4.5: v1(3228.35,-1783.46) 3342.52,-1783.46 3474.43,-1651.56 MC2.56@3474.43,-1558.65
  L8-BOT w4.5: v1(1504.04,-2825.36) 1504.04,-2797.68 1450.92,-2744.56 1450.92,-2588.45 1703.82,-2335.55 2014.76,-2335.55 2063.74,-2286.56 2063.74,-2022.87 2122.05,-1964.57 2153.54,-1964.57 2155.79,-1964.57 ccw(c2155.79,-1959.67) 2160.69,-1959.67 2160.69,-1944.47 cw(c2165.59,-1944.47) 2165.59,-1939.57 2180.29,-1939.57 cw(c2180.29,-1944.47) 2185.19,-1944.47 2185.19,-1984.67 ccw(c2190.09,-1984.67) 2190.09,-1989.57 2204.79,-1989.57 ccw(c2204.79,-1984.67) 2209.69,-1984.67 2209.69,-1944.47 cw(c2214.59,-1944.47) 2214.59,-1939.57 2229.29,-1939.57 cw(c2229.29,-1944.47) 2234.19,-1944.47 2234.19,-1984.67 ccw(c2239.09,-1984.67) 2239.09,-1989.57 2253.79,-1989.57 ccw(c2253.79,-1984.67) 2258.69,-1984.67 2258.69,-1944.47 cw(c2263.59,-1944.47) 2263.59,-1939.57 2278.29,-1939.57 cw(c2278.29,-1944.47) 2283.19,-1944.47 2283.19,-1984.67 ccw(c2288.09,-1984.67) 2288.09,-1989.57 2302.79,-1989.57 ccw(c2302.79,-1984.67) 2307.69,-1984.67 2307.69,-1944.47 cw(c2312.59,-1944.47) 2312.59,-1939.57 2327.29,-1939.57 cw(c2327.29,-1944.47) 2332.19,-1944.47 2332.19,-1984.67 ccw(c2337.09,-1984.67) 2337.09,-1989.57 2351.79,-1989.57 ccw(c2351.79,-1984.67) 2356.69,-1984.67 2356.69,-1944.47 cw(c2361.59,-1944.47) 2361.59,-1939.57 2376.29,-1939.57 cw(c2376.29,-1944.47) 2381.19,-1944.47 2381.19,-1983.9 ccw(c2386.09,-1983.9) 2386.09,-1988.8 2400.79,-1988.8 ccw(c2400.79,-1983.9) 2405.69,-1983.9 2405.69,-1969.47 cw(c2410.59,-1969.47) 2410.59,-1964.57 2484.25,-1964.57 3008.74,-1964.57 3047.2,-1926.1 3097.52,-1926.1 3228.35,-1795.28 v1(3228.35,-1783.46)
PORTB_S19: J4.24 MC2.36 | length 3377
  L1-TOP w4.5: v1(3244.11,-1609.94) 3269.99,-1609.94 3277.57,-1602.36 MC2.36@3277.57,-1558.65
  L8-BOT w4.5: v1(1504.04,-2599.76) 1504.04,-2566.82 1718.82,-2352.05 2021.6,-2352.05 2080.24,-2293.4 2080.24,-2187.47 2098.43,-2169.29 2103.87,-2169.29 2106.12,-2169.29 ccw(c2106.12,-2164.39) 2111.02,-2164.39 2111.02,-2149.19 cw(c2115.92,-2149.19) 2115.92,-2144.29 2130.62,-2144.29 cw(c2130.62,-2149.19) 2135.52,-2149.19 2135.52,-2189.39 ccw(c2140.42,-2189.39) 2140.42,-2194.29 2155.12,-2194.29 ccw(c2155.12,-2189.39) 2160.02,-2189.39 2160.02,-2149.19 cw(c2164.92,-2149.19) 2164.92,-2144.29 2179.62,-2144.29 cw(c2179.62,-2149.19) 2184.52,-2149.19 2184.52,-2189.39 ccw(c2189.42,-2189.39) 2189.42,-2194.29 2204.12,-2194.29 ccw(c2204.12,-2189.39) 2209.02,-2189.39 2209.02,-2149.19 cw(c2213.92,-2149.19) 2213.92,-2144.29 2228.62,-2144.29 cw(c2228.62,-2149.19) 2233.52,-2149.19 2233.52,-2189.39 ccw(c2238.42,-2189.39) 2238.42,-2194.29 2253.12,-2194.29 ccw(c2253.12,-2189.39) 2258.02,-2189.39 2258.02,-2149.19 cw(c2262.92,-2149.19) 2262.92,-2144.29 2277.62,-2144.29 cw(c2277.62,-2149.19) 2282.52,-2149.19 2282.52,-2189.39 ccw(c2287.42,-2189.39) 2287.42,-2194.29 2302.12,-2194.29 ccw(c2302.12,-2189.39) 2307.02,-2189.39 2307.02,-2149.19 cw(c2311.92,-2149.19) 2311.92,-2144.29 2326.62,-2144.29 cw(c2326.62,-2149.19) 2331.52,-2149.19 2331.52,-2189.39 ccw(c2336.42,-2189.39) 2336.42,-2194.29 2351.12,-2194.29 ccw(c2351.12,-2189.39) 2356.02,-2189.39 2356.02,-2174.19 cw(c2360.92,-2174.19) 2360.92,-2169.29 2373.17,-2169.29 2489,-2169.29 2491.25,-2169.29 ccw(c2491.25,-2164.39) 2496.15,-2164.39 2496.15,-2149.19 cw(c2501.05,-2149.19) 2501.05,-2144.29 2515.75,-2144.29 cw(c2515.75,-2149.19) 2520.65,-2149.19 2520.65,-2189.39 ccw(c2525.55,-2189.39) 2525.55,-2194.29 2540.25,-2194.29 ccw(c2540.25,-2189.39) 2545.15,-2189.39 2545.15,-2149.19 cw(c2550.05,-2149.19) 2550.05,-2144.29 2564.75,-2144.29 cw(c2564.75,-2149.19) 2569.65,-2149.19 2569.65,-2189.39 ccw(c2574.55,-2189.39) 2574.55,-2194.29 2589.25,-2194.29 ccw(c2589.25,-2189.39) 2594.15,-2189.39 2594.15,-2149.19 cw(c2599.05,-2149.19) 2599.05,-2144.29 2613.75,-2144.29 cw(c2613.75,-2149.19) 2618.65,-2149.19 2618.65,-2189.39 ccw(c2623.55,-2189.39) 2623.55,-2194.29 2638.25,-2194.29 ccw(c2638.25,-2189.39) 2643.15,-2189.39 2643.15,-2149.19 cw(c2648.05,-2149.19) 2648.05,-2144.29 2662.75,-2144.29 cw(c2662.75,-2149.19) 2667.65,-2149.19 2667.65,-2189.39 ccw(c2672.55,-2189.39) 2672.55,-2194.29 2687.25,-2194.29 ccw(c2687.25,-2189.39) 2692.15,-2189.39 2692.15,-2149.19 cw(c2697.05,-2149.19) 2697.05,-2144.29 2711.75,-2144.29 cw(c2711.75,-2149.19) 2716.65,-2149.19 2716.65,-2176.94 ccw(c2721.55,-2176.94) 2721.55,-2181.84 2736.25,-2181.84 ccw(c2736.25,-2176.94) 2741.15,-2176.94 2741.15,-2174.19 cw(c2746.05,-2174.19) 2746.05,-2169.29 2791.13,-2169.29 2917.7,-2169.29 2963.06,-2123.93 2963.06,-2033.58 3054.04,-1942.6 3105.18,-1942.6 3263.78,-1784 3263.78,-1629.61 v1(3244.11,-1609.94)
PORTB_S20: J4.25 MC2.35 | length 3377.2
  L1-TOP w4.5: MC2.35@3277.57,-1315.34 3277.97,-1314.94 3277.97,-1272.08 v1(3278.37,-1271.68)
  L8-BOT w4.5: v1(1535.54,-2912.07) 1535.54,-2832.68 1549.47,-2818.74 1549.47,-2784.07 1575.3,-2758.24 1575.3,-2745.33 1597,-2723.63 1622.69,-2723.63 1708.66,-2637.66 1708.66,-2622.08 1877.99,-2452.76 1891.21,-2452.76 1917.96,-2452.76 cw(c1917.96,-2457.66) 1922.86,-2457.66 1922.86,-2472.86 ccw(c1927.76,-2472.86) 1927.76,-2477.76 1942.46,-2477.76 ccw(c1942.46,-2472.86) 1947.36,-2472.86 1947.36,-2456.73 cw(c1952.26,-2456.73) 1952.26,-2451.83 1966.96,-2451.83 cw(c1966.96,-2456.73) 1971.86,-2456.73 1971.86,-2472.86 ccw(c1976.76,-2472.86) 1976.76,-2477.76 1991.46,-2477.76 ccw(c1991.46,-2472.86) 1996.36,-2472.86 1996.36,-2456.73 cw(c2001.26,-2456.73) 2001.26,-2451.83 2015.96,-2451.83 cw(c2015.96,-2456.73) 2020.86,-2456.73 2020.86,-2472.86 ccw(c2025.76,-2472.86) 2025.76,-2477.76 2040.46,-2477.76 ccw(c2040.46,-2472.86) 2045.36,-2472.86 2045.36,-2456.73 cw(c2050.26,-2456.73) 2050.26,-2451.83 2064.96,-2451.83 cw(c2064.96,-2456.73) 2069.86,-2456.73 2069.86,-2469.76 ccw(c2074.76,-2469.76) 2074.76,-2474.66 2089.46,-2474.66 ccw(c2089.46,-2469.76) 2094.36,-2469.76 2094.36,-2457.66 cw(c2099.26,-2457.66) 2099.26,-2452.76 2152.6,-2452.76 2909.45,-2452.76 2909.75,-2453.06 3186.54,-2176.27 3186.54,-2001.25 3399.89,-1787.9 3399.89,-1718.22 3454.26,-1663.85 3454.26,-1402.47 3366.75,-1314.96 3299.21,-1314.96 3278.37,-1294.12 v1(3278.37,-1271.68)
PORTB_S21: J4.26 MC2.48 | length 3377
  L1-TOP w4.5: v1(3339.08,-1683.29) 3339.08,-1637.31 3358.38,-1618.02 3375.69,-1618.02 3395.69,-1598.02 MC2.48@3395.69,-1558.65
  L8-BOT w4.5: v1(1535.54,-2686.47) 1606.48,-2615.53 1606.48,-2590.37 1657.1,-2539.75 1658.69,-2538.16 ccw(c1655.22,-2534.7) 1658.69,-2531.23 1655.78,-2528.32 cw(c1659.24,-2524.86) 1655.78,-2521.39 1666.17,-2511 cw(c1669.64,-2514.46) 1673.1,-2511 1693.69,-2531.59 ccw(c1697.15,-2528.12) 1700.62,-2531.59 1711.01,-2521.19 ccw(c1707.55,-2517.73) 1711.01,-2514.26 1690.42,-2493.68 cw(c1693.89,-2490.21) 1690.42,-2486.75 1700.82,-2476.35 cw(c1704.28,-2479.82) 1707.75,-2476.35 1728.34,-2496.94 ccw(c1731.8,-2493.47) 1735.27,-2496.94 1745.66,-2486.54 ccw(c1742.2,-2483.08) 1745.66,-2479.62 1726.36,-2460.31 cw(c1729.82,-2456.85) 1726.36,-2453.38 1736.75,-2442.99 cw(c1740.22,-2446.45) 1743.68,-2442.99 1745.31,-2444.61 ccw(c1748.77,-2441.15) 1752.24,-2444.61 1783.46,-2413.39 1794.52,-2402.33 2042.88,-2402.33 2122.37,-2322.83 2703.08,-2322.83 2705.33,-2322.83 ccw(c2705.33,-2317.93) 2710.23,-2317.93 2710.23,-2302.73 cw(c2715.13,-2302.73) 2715.13,-2297.83 2729.83,-2297.83 cw(c2729.83,-2302.73) 2734.73,-2302.73 2734.73,-2340.8 ccw(c2739.63,-2340.8) 2739.63,-2345.7 2754.33,-2345.7 ccw(c2754.33,-2340.8) 2759.23,-2340.8 2759.23,-2302.73 cw(c2764.13,-2302.73) 2764.13,-2297.83 2778.83,-2297.83 cw(c2778.83,-2302.73) 2783.73,-2302.73 2783.73,-2340.8 ccw(c2788.63,-2340.8) 2788.63,-2345.7 2803.33,-2345.7 ccw(c2803.33,-2340.8) 2808.23,-2340.8 2808.23,-2302.73 cw(c2813.13,-2302.73) 2813.13,-2297.83 2827.83,-2297.83 cw(c2827.83,-2302.73) 2832.73,-2302.73 2832.73,-2340.8 ccw(c2837.63,-2340.8) 2837.63,-2345.7 2852.33,-2345.7 ccw(c2852.33,-2340.8) 2857.23,-2340.8 2857.23,-2302.73 cw(c2862.13,-2302.73) 2862.13,-2297.83 2876.83,-2297.83 cw(c2876.83,-2302.73) 2881.73,-2302.73 2881.73,-2340.8 ccw(c2886.63,-2340.8) 2886.63,-2345.7 2901.33,-2345.7 ccw(c2901.33,-2340.8) 2906.23,-2340.8 2906.23,-2302.73 cw(c2911.13,-2302.73) 2911.13,-2297.83 2925.83,-2297.83 cw(c2925.83,-2302.73) 2930.73,-2302.73 2930.73,-2332.68 ccw(c2935.63,-2332.68) 2935.63,-2337.58 2950.33,-2337.58 ccw(c2950.33,-2332.68) 2955.23,-2332.68 2955.23,-2327.73 cw(c2960.13,-2327.73) 2960.13,-2322.83 2969.98,-2322.83 3022.42,-2270.39 3024.01,-2268.8 ccw(c3020.55,-2265.33) 3024.01,-2261.87 3016.03,-2253.88 cw(c3019.49,-2250.42) 3016.03,-2246.95 3026.42,-2236.56 cw(c3029.89,-2240.02) 3033.35,-2236.56 3041.34,-2244.54 ccw(c3044.8,-2241.08) 3048.27,-2244.54 3058.66,-2234.15 ccw(c3055.2,-2230.69) 3058.66,-2227.22 3016.03,-2184.59 cw(c3019.49,-2181.12) 3016.03,-2177.66 3026.42,-2167.26 cw(c3029.89,-2170.73) 3033.35,-2167.26 3075.99,-2209.9 ccw(c3079.45,-2206.43) 3082.92,-2209.9 3093.31,-2199.5 ccw(c3089.85,-2196.04) 3093.31,-2192.57 3065.39,-2164.65 cw(c3068.86,-2161.19) 3065.39,-2157.72 3075.79,-2147.33 cw(c3079.25,-2150.79) 3082.72,-2147.33 3110.64,-2175.25 ccw(c3114.1,-2171.78) 3117.57,-2175.25 3132.89,-2159.92 3137.04,-2155.77 3137.04,-1980.74 3339.08,-1778.7 v1(3339.08,-1683.29)
PORTB_S22: J4.27 MC2.49 | length 3377.2
  L1-TOP w4.5: MC2.49@3415.21,-1315.5 3415.21,-1266 v1(3415.3,-1265.9)
  L8-BOT w4.5: v1(1567.04,-2825.36) 1567.04,-2795.16 1581.19,-2781.01 1622.33,-2781.01 1638.23,-2765.12 1638.23,-2738.08 1666.56,-2709.75 1774.74,-2709.75 1801.39,-2683.1 1801.39,-2552.17 1801.39,-2548.03 1847.8,-2501.62 2647.76,-2501.62 2650.01,-2501.62 ccw(c2650.01,-2496.72) 2654.91,-2496.72 2654.91,-2481.52 cw(c2659.81,-2481.52) 2659.81,-2476.62 2674.51,-2476.62 cw(c2674.51,-2481.52) 2679.41,-2481.52 2679.41,-2518.45 ccw(c2684.31,-2518.45) 2684.31,-2523.35 2699.01,-2523.35 ccw(c2699.01,-2518.45) 2703.91,-2518.45 2703.91,-2481.52 cw(c2708.81,-2481.52) 2708.81,-2476.62 2723.51,-2476.62 cw(c2723.51,-2481.52) 2728.41,-2481.52 2728.41,-2518.45 ccw(c2733.31,-2518.45) 2733.31,-2523.35 2748.01,-2523.35 ccw(c2748.01,-2518.45) 2752.91,-2518.45 2752.91,-2481.52 cw(c2757.81,-2481.52) 2757.81,-2476.62 2772.51,-2476.62 cw(c2772.51,-2481.52) 2777.41,-2481.52 2777.41,-2516.03 ccw(c2782.31,-2516.03) 2782.31,-2520.93 2797.01,-2520.93 ccw(c2797.01,-2516.03) 2801.91,-2516.03 2801.91,-2496.72 cw(c2806.81,-2496.72) 2806.81,-2491.82 2821.51,-2491.82 cw(c2821.51,-2496.72) 2826.41,-2496.72 ccw(c2831.31,-2496.72) 2831.31,-2501.62 2869.89,-2501.62 2884.78,-2501.62 3203.22,-2183.18 3203.22,-2008.15 3416.57,-1794.8 3416.57,-1725.12 3470.94,-1670.76 3470.94,-1395.56 3415.3,-1339.93 v1(3415.3,-1265.9)
PORTB_S23: J4.28 MC2.46 | length 3376.9
  L1-TOP w4.5: v1(3304.3,-1683.79) 3304.3,-1646.86 3347.3,-1603.86 3368.59,-1603.86 3376.07,-1596.37 MC2.46@3376.07,-1558.71
  L8-BOT w4.5: v1(1567.04,-2599.76) 1567.04,-2574.69 1755.91,-2385.83 2036.05,-2385.83 2113.24,-2308.63 2113.24,-2291.32 2132.91,-2271.65 2135.16,-2271.65 ccw(c2135.16,-2266.75) 2140.06,-2266.75 2140.06,-2251.55 cw(c2144.96,-2251.55) 2144.96,-2246.65 2159.66,-2246.65 cw(c2159.66,-2251.55) 2164.56,-2251.55 2164.56,-2291.75 ccw(c2169.46,-2291.75) 2169.46,-2296.65 2184.16,-2296.65 ccw(c2184.16,-2291.75) 2189.06,-2291.75 2189.06,-2251.55 cw(c2193.96,-2251.55) 2193.96,-2246.65 2208.66,-2246.65 cw(c2208.66,-2251.55) 2213.56,-2251.55 2213.56,-2291.75 ccw(c2218.46,-2291.75) 2218.46,-2296.65 2233.16,-2296.65 ccw(c2233.16,-2291.75) 2238.06,-2291.75 2238.06,-2251.55 cw(c2242.96,-2251.55) 2242.96,-2246.65 2257.66,-2246.65 cw(c2257.66,-2251.55) 2262.56,-2251.55 2262.56,-2291.75 ccw(c2267.46,-2291.75) 2267.46,-2296.65 2282.16,-2296.65 ccw(c2282.16,-2291.75) 2287.06,-2291.75 2287.06,-2251.55 cw(c2291.96,-2251.55) 2291.96,-2246.65 2306.66,-2246.65 cw(c2306.66,-2251.55) 2311.56,-2251.55 2311.56,-2291.75 ccw(c2316.46,-2291.75) 2316.46,-2296.65 2331.16,-2296.65 ccw(c2331.16,-2291.75) 2336.06,-2291.75 2336.06,-2251.55 cw(c2340.96,-2251.55) 2340.96,-2246.65 2355.66,-2246.65 cw(c2355.66,-2251.55) 2360.56,-2251.55 2360.56,-2291.75 ccw(c2365.46,-2291.75) 2365.46,-2296.65 2380.16,-2296.65 ccw(c2380.16,-2291.75) 2385.06,-2291.75 2385.06,-2251.55 cw(c2389.96,-2251.55) 2389.96,-2246.65 2404.66,-2246.65 cw(c2404.66,-2251.55) 2409.56,-2251.55 2409.56,-2291.75 ccw(c2414.46,-2291.75) 2414.46,-2296.65 2429.16,-2296.65 ccw(c2429.16,-2291.75) 2434.06,-2291.75 2434.06,-2251.55 cw(c2438.96,-2251.55) 2438.96,-2246.65 2453.66,-2246.65 cw(c2453.66,-2251.55) 2458.56,-2251.55 2458.56,-2291.75 ccw(c2463.46,-2291.75) 2463.46,-2296.65 2478.16,-2296.65 ccw(c2478.16,-2291.75) 2483.06,-2291.75 2483.06,-2251.55 cw(c2487.96,-2251.55) 2487.96,-2246.65 2502.66,-2246.65 cw(c2502.66,-2251.55) 2507.56,-2251.55 2507.56,-2291.75 ccw(c2512.46,-2291.75) 2512.46,-2296.65 2527.16,-2296.65 ccw(c2527.16,-2291.75) 2532.06,-2291.75 2532.06,-2266.87 cw(c2536.96,-2266.87) 2536.96,-2261.97 2551.66,-2261.97 cw(c2551.66,-2266.87) 2556.56,-2266.87 2556.56,-2291.75 ccw(c2561.46,-2291.75) 2561.46,-2296.65 2576.16,-2296.65 ccw(c2576.16,-2291.75) 2581.06,-2291.75 2581.06,-2266.87 cw(c2585.96,-2266.87) 2585.96,-2261.97 2600.66,-2261.97 cw(c2600.66,-2266.87) 2605.56,-2266.87 2605.56,-2291.75 ccw(c2610.46,-2291.75) 2610.46,-2296.65 2625.16,-2296.65 ccw(c2625.16,-2291.75) 2630.06,-2291.75 2630.06,-2268.57 cw(c2634.96,-2268.57) 2634.96,-2263.67 2649.66,-2263.67 cw(c2649.66,-2268.57) 2654.56,-2268.57 2654.56,-2276.55 ccw(c2659.46,-2276.55) 2659.46,-2281.45 2674.16,-2281.45 ccw(c2674.16,-2276.55) 2679.06,-2276.55 cw(c2683.96,-2276.55) 2683.96,-2271.65 2739.46,-2271.65 2990.7,-2271.65 2996.06,-2266.29 2996.06,-2047.24 3066.93,-1976.38 3118.07,-1976.38 3304.3,-1790.15 v1(3304.3,-1683.79)
PORTB_S24: J4.29 MC2.51 | length 3377
  L1-TOP w4.5: MC2.51@3435.06,-1315.34 3435.06,-1225.85 v1(3435.22,-1225.69)
  L8-BOT w4.5: v1(1598.54,-2912.07) 1598.54,-2826.65 1622.05,-2803.15 1657.06,-2803.15 1730.1,-2730.11 1831.8,-2730.11 1889.76,-2672.15 1889.76,-2570.87 1920.78,-2539.85 1940.94,-2539.85 1943.2,-2539.85 ccw(c1943.2,-2534.95) 1948.1,-2534.95 1948.1,-2527.24 cw(c1953,-2527.24) 1953,-2522.34 1967.7,-2522.34 cw(c1967.7,-2527.24) 1972.6,-2527.24 1972.6,-2559.95 ccw(c1977.5,-2559.95) 1977.5,-2564.85 1992.2,-2564.85 ccw(c1992.2,-2559.95) 1997.1,-2559.95 1997.1,-2527.24 cw(c2002,-2527.24) 2002,-2522.34 2016.7,-2522.34 cw(c2016.7,-2527.24) 2021.6,-2527.24 2021.6,-2558.15 ccw(c2026.5,-2558.15) 2026.5,-2563.05 2041.2,-2563.05 ccw(c2041.2,-2558.15) 2046.1,-2558.15 2046.1,-2534.95 cw(c2051,-2534.95) 2051,-2530.05 2065.7,-2530.05 cw(c2065.7,-2534.95) 2070.6,-2534.95 ccw(c2075.5,-2534.95) 2075.5,-2539.85 2116.21,-2539.85 2869.89,-2539.85 3219.72,-2190.02 3219.72,-2014.99 3433.07,-1801.64 3433.07,-1731.96 3487.44,-1677.59 3487.44,-1388.72 3435.22,-1336.51 v1(3435.22,-1225.69)
PORTB_S25: J4.30 MC2.54 | length 3377
  L1-TOP w4.5: v1(3401.57,-1683.29) 3454.74,-1630.13 MC2.54@3454.74,-1558.65
  L8-BOT w4.5: v1(1598.54,-2686.47) 1647.36,-2637.66 1665.49,-2637.66 1867.82,-2435.33 2056.55,-2435.33 2087.81,-2404.07 2096.45,-2404.07 2098.7,-2404.07 ccw(c2098.7,-2399.17) 2103.6,-2399.17 2103.6,-2393.18 cw(c2108.5,-2393.18) 2108.5,-2388.28 2123.2,-2388.28 cw(c2123.2,-2393.18) 2128.1,-2393.18 2128.1,-2424.17 ccw(c2133,-2424.17) 2133,-2429.07 2147.7,-2429.07 ccw(c2147.7,-2424.17) 2152.6,-2424.17 2152.6,-2408.6 cw(c2157.5,-2408.6) 2157.5,-2403.7 2172.2,-2403.7 cw(c2172.2,-2408.6) 2177.1,-2408.6 2177.1,-2424.17 ccw(c2182,-2424.17) 2182,-2429.07 2196.7,-2429.07 ccw(c2196.7,-2424.17) 2201.6,-2424.17 2201.6,-2408.6 cw(c2206.5,-2408.6) 2206.5,-2403.7 2221.2,-2403.7 cw(c2221.2,-2408.6) 2226.1,-2408.6 2226.1,-2424.17 ccw(c2231,-2424.17) 2231,-2429.07 2245.7,-2429.07 ccw(c2245.7,-2424.17) 2250.6,-2424.17 2250.6,-2408.6 cw(c2255.5,-2408.6) 2255.5,-2403.7 2270.2,-2403.7 cw(c2270.2,-2408.6) 2275.1,-2408.6 2275.1,-2424.17 ccw(c2280,-2424.17) 2280,-2429.07 2294.7,-2429.07 ccw(c2294.7,-2424.17) 2299.6,-2424.17 2299.6,-2408.6 cw(c2304.5,-2408.6) 2304.5,-2403.7 2319.2,-2403.7 cw(c2319.2,-2408.6) 2324.1,-2408.6 2324.1,-2424.17 ccw(c2329,-2424.17) 2329,-2429.07 2343.7,-2429.07 ccw(c2343.7,-2424.17) 2348.6,-2424.17 2348.6,-2408.6 cw(c2353.5,-2408.6) 2353.5,-2403.7 2368.2,-2403.7 cw(c2368.2,-2408.6) 2373.1,-2408.6 2373.1,-2424.17 ccw(c2378,-2424.17) 2378,-2429.07 2392.7,-2429.07 ccw(c2392.7,-2424.17) 2397.6,-2424.17 2397.6,-2408.6 cw(c2402.5,-2408.6) 2402.5,-2403.7 2417.2,-2403.7 cw(c2417.2,-2408.6) 2422.1,-2408.6 2422.1,-2424.17 ccw(c2427,-2424.17) 2427,-2429.07 2441.7,-2429.07 ccw(c2441.7,-2424.17) 2446.6,-2424.17 2446.6,-2408.6 cw(c2451.5,-2408.6) 2451.5,-2403.7 2466.2,-2403.7 cw(c2466.2,-2408.6) 2471.1,-2408.6 2471.1,-2424.17 ccw(c2476,-2424.17) 2476,-2429.07 2490.7,-2429.07 ccw(c2490.7,-2424.17) 2495.6,-2424.17 2495.6,-2408.6 cw(c2500.5,-2408.6) 2500.5,-2403.7 2515.2,-2403.7 cw(c2515.2,-2408.6) 2520.1,-2408.6 2520.1,-2424.17 ccw(c2525,-2424.17) 2525,-2429.07 2539.7,-2429.07 ccw(c2539.7,-2424.17) 2544.6,-2424.17 2544.6,-2408.6 cw(c2549.5,-2408.6) 2549.5,-2403.7 2564.2,-2403.7 cw(c2564.2,-2408.6) 2569.1,-2408.6 2569.1,-2424.17 ccw(c2574,-2424.17) 2574,-2429.07 2588.7,-2429.07 ccw(c2588.7,-2424.17) 2593.6,-2424.17 2593.6,-2408.6 cw(c2598.5,-2408.6) 2598.5,-2403.7 2613.2,-2403.7 cw(c2613.2,-2408.6) 2618.1,-2408.6 2618.1,-2424.17 ccw(c2623,-2424.17) 2623,-2429.07 2637.7,-2429.07 ccw(c2637.7,-2424.17) 2642.6,-2424.17 2642.6,-2408.6 cw(c2647.5,-2408.6) 2647.5,-2403.7 2662.2,-2403.7 cw(c2662.2,-2408.6) 2667.1,-2408.6 2667.1,-2424.17 ccw(c2672,-2424.17) 2672,-2429.07 2686.7,-2429.07 ccw(c2686.7,-2424.17) 2691.6,-2424.17 2691.6,-2383.97 cw(c2696.5,-2383.97) 2696.5,-2379.07 2711.2,-2379.07 cw(c2711.2,-2383.97) 2716.1,-2383.97 2716.1,-2424.17 ccw(c2721,-2424.17) 2721,-2429.07 2735.7,-2429.07 ccw(c2735.7,-2424.17) 2740.6,-2424.17 2740.6,-2383.97 cw(c2745.5,-2383.97) 2745.5,-2379.07 2760.2,-2379.07 cw(c2760.2,-2383.97) 2765.1,-2383.97 2765.1,-2424.17 ccw(c2770,-2424.17) 2770,-2429.07 2784.7,-2429.07 ccw(c2784.7,-2424.17) 2789.6,-2424.17 2789.6,-2383.97 cw(c2794.5,-2383.97) 2794.5,-2379.07 2809.2,-2379.07 cw(c2809.2,-2383.97) 2814.1,-2383.97 2814.1,-2424.17 ccw(c2819,-2424.17) 2819,-2429.07 2833.7,-2429.07 ccw(c2833.7,-2424.17) 2838.6,-2424.17 2838.6,-2387.92 cw(c2843.5,-2387.92) 2843.5,-2383.02 2858.2,-2383.02 cw(c2858.2,-2387.92) 2863.1,-2387.92 2863.1,-2408.97 ccw(c2868,-2408.97) 2868,-2413.87 2882.7,-2413.87 ccw(c2882.7,-2408.97) 2887.6,-2408.97 cw(c2892.5,-2408.97) 2892.5,-2404.07 2925.2,-2404.07 2935.41,-2404.07 3170.04,-2169.44 3170.04,-1994.41 3381.92,-1782.53 3381.92,-1702.95 v1(3401.57,-1683.29)
PORTB_S26: J4.31 MC2.53 | length 3377.2
  L1-TOP w4.5: MC2.53@3454.58,-1315.5 3454.58,-1266 v1(3454.67,-1265.9)
  L8-BOT w4.5: v1(1630.04,-2825.36) 1712.33,-2825.36 1750.29,-2787.4 1822.83,-2787.4 1906.26,-2703.97 1906.26,-2613.42 1927.63,-2592.06 2263.78,-2592.06 2266.03,-2592.06 ccw(c2266.03,-2587.16) 2270.93,-2587.16 2270.93,-2571.96 cw(c2275.83,-2571.96) 2275.83,-2567.06 2290.53,-2567.06 cw(c2290.53,-2571.96) 2295.43,-2571.96 2295.43,-2612.16 ccw(c2300.33,-2612.16) 2300.33,-2617.06 2315.03,-2617.06 ccw(c2315.03,-2612.16) 2319.93,-2612.16 2319.93,-2571.96 cw(c2324.83,-2571.96) 2324.83,-2567.06 2339.53,-2567.06 cw(c2339.53,-2571.96) 2344.43,-2571.96 2344.43,-2612.16 ccw(c2349.33,-2612.16) 2349.33,-2617.06 2364.03,-2617.06 ccw(c2364.03,-2612.16) 2368.93,-2612.16 2368.93,-2571.96 cw(c2373.83,-2571.96) 2373.83,-2567.06 2388.53,-2567.06 cw(c2388.53,-2571.96) 2393.43,-2571.96 2393.43,-2612.16 ccw(c2398.33,-2612.16) 2398.33,-2617.06 2413.03,-2617.06 ccw(c2413.03,-2612.16) 2417.93,-2612.16 2417.93,-2571.96 cw(c2422.83,-2571.96) 2422.83,-2567.06 2437.53,-2567.06 cw(c2437.53,-2571.96) 2442.43,-2571.96 2442.43,-2603.94 ccw(c2447.33,-2603.94) 2447.33,-2608.84 2462.03,-2608.84 ccw(c2462.03,-2603.94) 2466.93,-2603.94 2466.93,-2596.96 cw(c2471.83,-2596.96) 2471.83,-2592.06 2515.75,-2592.06 2841.02,-2592.06 3236.22,-2196.85 3236.22,-2021.82 3449.57,-1808.47 3449.57,-1738.79 3503.94,-1684.43 3503.94,-1381.89 3454.67,-1332.63 v1(3454.67,-1265.9)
